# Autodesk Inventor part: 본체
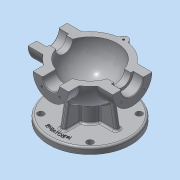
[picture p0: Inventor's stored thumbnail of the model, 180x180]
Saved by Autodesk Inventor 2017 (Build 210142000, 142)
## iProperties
Created: 2015-12
Part Number: 본체
Material: 알루미늄 6061
Document SubType Name: Modeling
Designer: mduedu
Density: 2.71 g/cm^3
Appearance: 알루미늄 - 평지
Mass: 966.367 g
Surface Area: 788.536 cm^2
Volume: 356.593 cm^3
Author: mduedu
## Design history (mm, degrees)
sketch "스케치1"
  geometry: L1 (-53, 0)-(53, 0); A1 r 53 centre (0, 0) between (53, 0) and (-53, 0); 2 further points
  constraints: 2 coincident, 2 end point, 2 point on circle, 1 centre point, 1 horizontal, 1 midpoint
  dimensions: "d0" = 53 radius of A1
revolve "회전1" sketch "스케치1" stored, may be unused: angle "d2" = 90 deg
feature "쉘1" dims "d11" = 10
node "작업 평면1"
sketch "스케치2"
  geometry: C1 r 31 at (0, 0); 1 further point
  constraints: 1 centre point, 1 coincident
  dimensions: "d4" = 62 diameter of C1
extrude "돌출1" join sketch "스케치2" stored distance "d5" = 10; taper "d6" = 0 deg
node "작업 평면2"
sketch "스케치3"
  geometry: C1 r 28 at (0, 0); 1 further point
  constraints: 1 centre point, 1 coincident
  dimensions: "d8" = 56 diameter of C1
extrude "돌출2" join sketch "스케치3" stored distance "d9" = 10; taper "d10" = 0 deg
hole "구멍1" diameter "d14" = 35; stored, may be unused: countersink angle "d18" = 90 deg, drill point angle "d20" = 0 deg; dims "d12" = 10, "d13" = 10, "d15" = 6, "d16" = 4, "d17" = 2, "d19" = 16
hole "구멍2" diameter "d23" = 27; stored, may be unused: countersink angle "d27" = 90 deg, drill point angle "d29" = 0 deg; dims "d21" = 10, "d22" = 10, "d24" = 6, "d25" = 4, "d26" = 2, "d28" = 16
fillet "모깎기1" dims "d30" = 0.3
hole "구멍3" diameter "d33" = 26; stored, may be unused: countersink angle "d37" = 90 deg, drill point angle "d39" = 0 deg; dims "d31" = 10, "d32" = 10, "d34" = 6, "d35" = 4, "d36" = 2, "d38" = 16
chamfer "모따기1" distance "d40" = 1; stored, may be unused: second distance "d41" = 2, angle "d42" = 45 deg
sketch "스케치4"
  geometry: L1 (0, 0)-(0, -25); L2 (0, 0)-(-17.678, -17.678); A1 r 25 centre (0, 0) between (-17.678, -17.678) and (0, -25); 1 further point
  constraints: 4 end point, 2 point on circle, 1 centre point, 1 coincident, 1 vertical
  dimensions: "d43" = 50 diameter of A1; "d47" = 45 deg angle of L1 L2
hole "구멍4" sketch "스케치4" at (-17.678, -17.678) diameter "d49" = 3.242; stored, may be unused: countersink angle "d53" = 90 deg, drill point angle "d55" = 118 deg; dims "d50" = 11, "d51" = 4, "d52" = 2, "d54" = 13
sketch "스케치5"
  geometry: L1 (0, 0)-(0, -20); L2 (0, 0)-(-14.142, -14.142); A1 r 20 centre (0, 0) between (0, -20) and (-14.142, -14.142); 2 further points
  constraints: 4 end point, 2 coincident, 2 point on circle, 1 centre point, 1 vertical
  dimensions: "d59" = 40 diameter of A1; "d65" = 45 deg angle of L1 L2
hole "구멍5" sketch "스케치5" at (-14.142, -14.142) diameter "d67" = 3.242; stored, may be unused: countersink angle "d71" = 90 deg, drill point angle "d73" = 118 deg; dims "d68" = 8, "d69" = 4, "d70" = 2, "d72" = 10
node "작업 평면3"
sketch "스케치6"
  geometry: C1 r 65 at (0, 0); 1 further point
  constraints: 1 centre point, 1 coincident
  dimensions: "d78" = 130 diameter of C1
extrude "돌출3" join sketch "스케치6" distance "d80" = 10; taper "d81" = 0 deg
sketch "스케치7"
  geometry: C1 r 20 at (0, 0); 1 further point
  constraints: 1 centre point, 1 coincident
  dimensions: "d82" = 40 diameter of C1
extrude "돌출4" join sketch "스케치7" stored distance "d84" = 10; taper "d85" = 0 deg
sketch "스케치8"
  geometry: 2 further points
  constraints: 1 coincident
hole "구멍6" sketch "스케치8" at (0, 0) diameter "d86" = 20; stored, may be unused: countersink angle "d90" = 90 deg, drill point angle "d92" = 118 deg; dims "d87" = 7, "d88" = 40, "d89" = 5, "d91" = 10
fillet "모깎기2" dims "d93" = 0.3
sketch "스케치9"
  geometry: L1 (65, -75)-(-65, -75) reference; L2 (-45, -75)-(-38.245, -36.692); A1 r 53 centre (0, 0) between (42.988, 31) and (42.988, -31) reference; 1 further point
  constraints: 2 end point, 1 point on circle, 1 point on line
  dimensions: "d94" = 45 horizontal distance of L2.start point (0, 0); "d95" = 80 deg angle of L2 L1
feature "리브1" sketch "스케치9" dims "d96" = 1, "d97" = 8, "d98" = 0, "d99" = 0, "d100" = 1, "d101" = 1
sketch "스케치10"
  geometry: L1 (0, 0)-(0, -55); L2 (0, 0)-(-38.891, -38.891); A1 r 55 centre (0, 0) between (0, -55) and (-38.891, -38.891); 2 further points
  constraints: 4 end point, 2 coincident, 2 point on circle, 1 centre point, 1 vertical
  dimensions: "d105" = 110 diameter of A1; "d107" = 45 deg angle of L1 L2
hole "구멍7" sketch "스케치10" at (-38.891, -38.891) diameter "d109" = 10; stored, may be unused: countersink angle "d113" = 90 deg, drill point angle "d115" = 118 deg; dims "d110" = 7, "d111" = 40, "d112" = 5, "d114" = 10
fillet "모깎기3" dims "d120" = 3
fillet "모깎기4" dims "d121" = 3, "d122" = 3
fillet "모깎기5" dims "d123" = 3
fillet "모깎기6" dims "d124" = 3
sketch "스케치11"
  geometry: C1 r 5 at (-38.891, 38.891) reference; C2 r 5 at (38.891, 38.891) reference; C3 r 5 at (38.891, -38.891) reference; C4 r 5 at (-38.891, -38.891) reference; C5 r 20 at (0, 0) reference; C6 r 65 at (0, 0) reference; 1 further point
  constraints: 3 other
feature "엠보싱1" sketch "스케치11" dims "d125" = 0.5, "d126" = 0
sketch "스케치12"
  geometry: L1 (0, 100)-(0, -100); L2 (0, 100)-(100, 100); L3 (100, 100)-(100, -100); L4 (100, -100)-(0, -100); 2 further points
  constraints: 8 end point, 3 perpendicular, 1 coincident, 1 midpoint, 1 vertical
  dimensions: "d127" = 200 distance of L2.end L3.end; "d129" = 100 distance between parallel lines of L1 L3
extrude "돌출5" cut sketch "스케치12" stored distance "d130" = 10; taper "d131" = 0 deg
sketch "스케치13"
  geometry: C1 r 7 at (0, 53); A1 r 53 centre (0, 0) between (42.113, 32.179) and (-42.113, 32.179) reference; 1 further point
  constraints: 1 centre point, 1 point on circle
  dimensions: "d132" = 14 diameter of C1
extrude "돌출6" join sketch "스케치13" distance "d134" = 15; taper "d135" = 0 deg
hole "구멍8" diameter "d139" = 3.242; stored, may be unused: countersink angle "d143" = 90 deg, drill point angle "d145" = 118 deg; dims "d140" = 8, "d141" = 4, "d142" = 2, "d144" = 10, "d148" = 10, "d149" = 10
fillet "모깎기7" dims "d146" = 3
fillet "모깎기8" dims "d147" = 3
node "솔리드1"
mirror "대칭1"
mirror "대칭2"
pattern_circular "원형 패턴1" dims angle "d57" = 360 deg
mirror "대칭3"
pattern_circular "원형 패턴2" dims angle "d75" = 360 deg
pattern_circular "원형 패턴3" dims angle "d103" = 360 deg
pattern_circular "원형 패턴4" dims angle "d118" = 360 deg
node "투영된 루프1"
other parameters: "d3" = 67, "d7" = 62, "d77" = -85
